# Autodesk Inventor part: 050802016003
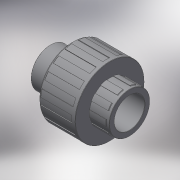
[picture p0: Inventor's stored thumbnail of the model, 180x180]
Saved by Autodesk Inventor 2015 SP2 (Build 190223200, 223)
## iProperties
Created: 2017-10
Part Number: 050802016003
Material: Generic
Description: PLASSON UNION+O RING THR-CEM 16-3/8
Document SubType Name: Modeling
Designer: KIM
Density: 1 g/cm^3
Appearance: Default
Author: KIM
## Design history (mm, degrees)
derived "050802.ipt"
feature "Solid1::050802.ipt"
tag "TaggingFeature1"
body "Solid1"
other parameters: "d0" = 39, "d3" = 16, "d4" = 14.95, "d5" = 19.2, "d7" = 20.48, "d8" = 34, "d9" = 14, "d10" = 13, "d11" = 13.6, "d12" = 15.2, "d14" = 9.75, "d15" = 10.5, "d16" = 10.8, "d17" = 1.3, "d19" = 33.32, "d20" = 1.4, "d21" = 1.02, "d25" = 3.4, "d26" = 1.7, "d27" = 15.615, "d28" = 0, "d32" = 3.4, "d33" = 1.7, "d35" = 0, "d39" = 0.16, "d45" = 0.24, "d49" = 360 deg, "d51" = 0.34, "d55" = 360 deg, "d_" = 16, "E_" = 34, "H_" = 39, "l_" = 14, "lt_" = 13, "Z_" = 11, "G_" = 14.95, "d13" = 12, "d24" = 17.35, "d40" = 0.24, "d44" = 0.34
